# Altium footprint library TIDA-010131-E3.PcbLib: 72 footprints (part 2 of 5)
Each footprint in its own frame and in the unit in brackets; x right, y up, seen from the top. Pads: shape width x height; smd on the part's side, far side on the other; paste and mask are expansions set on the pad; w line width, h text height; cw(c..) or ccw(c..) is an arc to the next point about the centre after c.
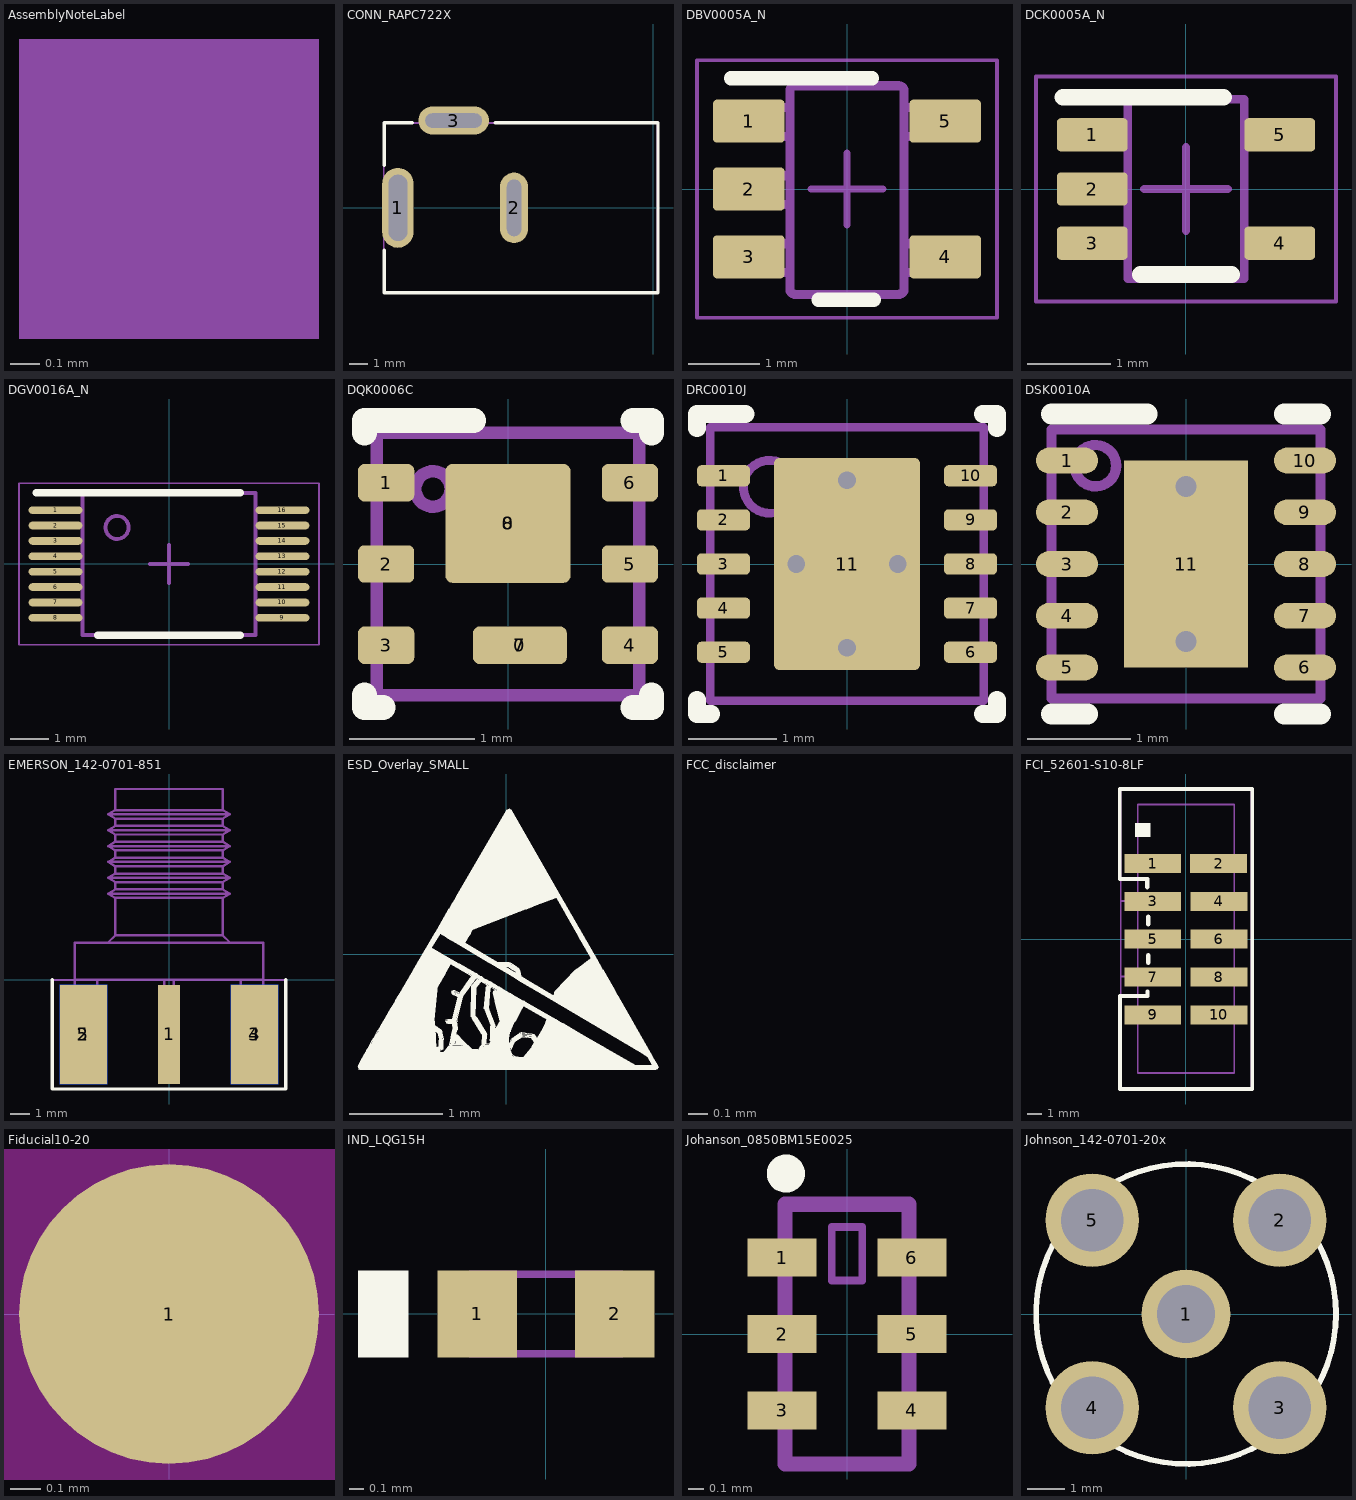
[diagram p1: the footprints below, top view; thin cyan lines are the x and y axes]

## AssemblyNoteLabel [mm] "Assembly Note for PCB Labels"
Mechanical 5:
  rectangle: 15.799,83.744 16.815,84.76
  text ".Designator" at 11.913,83.845 h0.64
  text "Install label in silkscreened box after final wash.  Text shall be 8 pt font.  Text shall be per the Label Table in the PDF schematic." at 17.755,83.896 h0.64

## CONN_RAPC722X [mm] "Conn_DC Jack"
height 11.176
pads (3):
  oval 1.7x4.3 hole 1.01 slot 3.56 at 90 deg: 1(-13.741,0)
  oval 1.5x3.8 hole 0.76 slot 3.05 at 90 deg: 2(-7.493,0)
  oval 3.8x1.5 hole 0.76 slot 3.05 at 0 deg: 3(-10.744,4.7)
Top Overlay:
  lines w0.178: -14.478,-2.286 -14.478,-4.572 0.254,-4.572 0.254,4.572 -8.509,4.572 ; -14.478,2.286 -14.478,4.572 -12.954,4.572
Mechanical 5:
  lines w0.102: -14.505,-4.572 -14.505,4.572 0.227,4.572 0.227,-4.572 -14.505,-4.572
  lines w0.127: -14.443,-1.5 -13.943,-1.5 ; -14.443,1.5 -13.943,1.5 ; -13.543,-1.5 -13.943,-1.5 ; -13.543,1.5 -13.943,1.5 ; -11.993,4.5 -11.993,4.9 -9.493,4.9 -9.493,4.5 ; -13.943,-1.5 -13.943,1.5
  text ".Designator" at -12.446,-0.508 h0.64
3D body: height 11.18, standoff 0, extent -14.504,-4.571 0.226,4.571
3D body: height 5.08, standoff -2.54, extent -7.62,-1.397 -7.366,1.397
3D body: height 5.08, standoff -2.54, extent -12.14,4.573 -9.346,4.827
3D body: height 5.08, standoff -2.54, extent -14.06,-1.651 -13.425,1.651

## DBV0005A_N [mm] "SOT23, 5-Leads, Body 2.9x1.6mm, Pitch 0.95mm, Lead Span 2.8mm, IPC Medium Density"
height 1.45
pads (5):
  rrect17% 1x0.6 smd: 1(-1.375,0.95) 2(-1.375,0) 3(-1.375,-0.95) 4(1.375,-0.95) 5(1.375,0.95)
Top Overlay:
  lines w0.2: -1.625,1.55 0.35,1.55 ; -0.4,-1.55 0.375,-1.55
Mechanical 5:
  lines w0.127: -0.801,1.371 cw(c-0.725,1.37) -0.725,1.446 ; -0.801,1.37 -0.801,1.371 ; -0.801,1.37 -0.801,-1.399 -0.801,-1.4 ccw(c-0.725,-1.399) -0.725,-1.475 ; -0.725,-1.475 0.723,-1.475 0.724,-1.475 ccw(c0.723,-1.399) 0.799,-1.4 0.799,-1.399 0.799,1.37 ; -0.725,-1.475 -0.725,-1.475 ; -0.725,1.446 -0.725,1.446 ; -0.725,1.446 0.723,1.446 0.724,1.446 cw(c0.723,1.37) 0.799,1.371 ; 0.799,1.37 0.799,1.371 ; -1.423,-1.167 -1.423,-0.767 -1.199,-0.767 -1.105,-0.767 -1.088,-0.767 -0.835,-0.767 -0.801,-0.767 -0.801,-1.167 -0.835,-1.167 -1.088,-1.167 -1.105,-1.167 -1.199,-1.167 -1.423,-1.167 ; -1.423,-0.215 -1.423,0.186 -1.199,0.186 -1.105,0.186 -1.088,0.186 -0.835,0.186 -0.801,0.186 -0.801,-0.215 -0.835,-0.215 -1.088,-0.215 -1.105,-0.215 -1.199,-0.215 -1.423,-0.215 ; -1.423,0.738 -1.423,1.138 -1.199,1.138 -1.105,1.138 -1.088,1.138 -0.835,1.138 -0.801,1.138 -0.801,0.738 -0.835,0.738 -1.088,0.738 -1.105,0.738 -1.199,0.738 -1.423,0.738 ; 0.799,-1.167 0.834,-1.167 1.087,-1.167 1.103,-1.167 1.198,-1.167 1.422,-1.167 1.422,-0.767 1.198,-0.767 1.103,-0.767 1.087,-0.767 0.834,-0.767 0.799,-0.767 0.799,-1.167 ; 0.799,0.738 0.834,0.738 1.087,0.738 1.103,0.738 1.198,0.738 1.422,0.738 1.422,1.138 1.198,1.138 1.103,1.138 1.087,1.138 0.834,1.138 0.799,1.138 0.799,0.738
  text ".Designator" at 0.356,-0.571 h0.64
Mechanical 15:
  lines w0.05: -2.1,-1.8 -2.1,1.8 2.1,1.8 2.1,-1.8 -2.1,-1.8
  lines w0.1: -0.5,0 0.5,0 ; 0,-0.5 0,0.5
3D body "DBV0005A.stp": height 1.09, standoff 0, extent -1.422,-1.461 1.423,1.46

## DCK0005A_N [mm] "SOT353, 5-Leads, Body 2x1.3mm, Pitch 0.65mm, Lead Span 2.1mm, IPC Medium Density"
height 1.1
pads (5):
  rrect25% 0.85x0.4 smd: 1(-1.125,0.65) 2(-1.125,0) 3(-1.125,-0.65) 4(1.125,-0.65) 5(1.125,0.65)
Top Overlay:
  lines w0.2: -1.475,1.1 0.45,1.1 ; -0.55,-1.025 0.55,-1.025
Mechanical 5:
  lines w0.1: -0.7,-1.075 0.7,-1.075 0.7,1.075 -0.7,1.075 -0.7,-1.075
  lines w0.127: -0.865,0.762 -0.853,0.762 ; -0.711,-0.763 -0.853,-0.763 -0.865,-0.763 -0.959,-0.763 -1.143,-0.763 -1.143,-0.538 -0.959,-0.538 -0.865,-0.538 -0.853,-0.538 -0.711,-0.538 ; -0.711,-0.113 -0.853,-0.113 -0.865,-0.113 -0.959,-0.113 -1.143,-0.113 -1.143,0.112 -0.959,0.112 -0.865,0.112 -0.853,0.112 -0.711,0.112 ; -0.711,0.537 -0.853,0.537 -0.865,0.537 -0.959,0.537 -1.143,0.537 -1.143,0.762 -0.959,0.762 -0.711,0.762 ; 0.711,-0.763 0.847,-0.763 0.859,-0.763 0.953,-0.763 1.137,-0.763 1.137,-0.538 0.953,-0.538 0.859,-0.538 0.847,-0.538 0.711,-0.538 ; 0.711,0.537 0.847,0.537 0.859,0.537 0.953,0.537 1.137,0.537 1.137,0.762 0.953,0.762 0.859,0.762 0.847,0.762 0.711,0.762
  text ".Designator" at -0.254,0.824 h0.64
Mechanical 15:
  lines w0.05: -1.8,-1.35 1.8,-1.35 1.8,1.35 -1.8,1.35 -1.8,-1.35
  lines w0.1: -0.5,0 0.5,0 ; 0,-0.5 0,0.5
3D body "DCK0005A.stp": height 0.95, standoff 0, extent -1.14,-1 1.14,1

## DGV0016A_N [mm] "TSSOP, 16-Leads, Body 3.6x4.4mm, Pitch 0.4mm, IPC Medium Density"
height 1.2
pads (16):
  oval 1.4x0.2 smd: 1(-2.95,1.4) 2(-2.95,1) 3(-2.95,0.6) 4(-2.95,0.2) 5(-2.95,-0.2) 6(-2.95,-0.6) 7(-2.95,-1) 8(-2.95,-1.4) 9(2.95,-1.4) 10(2.95,-1) 11(2.95,-0.6) 12(2.95,-0.2) 13(2.95,0.2) 14(2.95,0.6) 15(2.95,1) 16(2.95,1.4)
Top Overlay:
  lines w0.2: -3.45,1.85 1.85,1.85 ; -1.85,-1.85 1.85,-1.85
Mechanical 5:
  circle w0.1: c-1.35,0.95 r0.3
  lines w0.1: -2.25,-1.85 2.25,-1.85 2.25,1.85 -2.25,1.85 -2.25,-1.85
  text ".Designator" at 0.781,-0.032 h0.64
Mechanical 15:
  lines w0.05: -3.9,-2.1 3.9,-2.1 3.9,2.1 -3.9,2.1 -3.9,-2.1
  lines w0.1: -0.5,0 0.5,0 ; 0,-0.5 0,0.5
3D body "DGV0016A.stp": height 1.2, standoff 0, extent -3.209,-1.8 3.209,1.8

## DQK0006C [mm] "WSON"
height 0.8
pads (10):
  rrect50% 0.9x0.86 on Top Paste: 0(0,0.325)
  rrect50% 0.7x0.29 on Top Paste: 0(0.095,-0.65)
  rrect33% 0.45x0.3 smd: 1(-0.975,0.65) 2(-0.975,0) 3(-0.975,-0.65) 4(0.975,-0.65) 5(0.975,0) 6(0.975,0.65)
  rrect33% 0.75x0.3 smd paste-0.15: 7(0.095,-0.65)
  rrect11% 1x0.95 smd paste-0.5: 8(0,0.325)
Top Overlay:
  lines w0.2: -1.15,-1.05 -1.15,-1.15 -1,-1.15 ; -1.15,1.05 -1.15,1.15 -0.275,1.15 ; 1,-1.15 1.15,-1.15 1.15,-1.05 ; 1,1.15 1.15,1.15 1.15,1.05
Mechanical 5:
  circle w0.1: c-0.6,0.6 r0.141
  lines w0.1: -1.05,-1.05 -1.05,1.05 1.05,1.05 1.05,-1.05 -1.05,-1.05
  text ".Designator" at 0.397,-0.417 h0.64
3D body "DQK0006C.stp": height 0.82, standoff 0, extent -1,-1 1,1

## DRC0010J [mm] "SON, 10-Leads, Body 3x3mm, Pitch 0.5mm, Thermal Pad 2.4x1.65mm, TI Recommended"
height 1
pads (11):
  rrect42% 0.6x0.24 smd: 1(-1.4,1) 2(-1.4,0.5) 3(-1.4,0) 4(-1.4,-0.5) 5(-1.4,-1) 6(1.4,-1) 7(1.4,-0.5) 8(1.4,0) 9(1.4,0.5) 10(1.4,1)
  rrect6% 1.65x2.4 smd paste-0.825: 11(0,0)
via 0,-0.95 diameter 0.5 hole 0.2
via 0,0.95 diameter 0.5 hole 0.2
via 0.575,0 diameter 0.5 hole 0.2
via -0.575,0 diameter 0.5 hole 0.2
Top Overlay:
  lines w0.2: -1.7,-1.54 -1.7,-1.7 -1.54,-1.7 ; -1.7,1.54 -1.7,1.7 -1.15,1.7 ; 1.54,-1.7 1.7,-1.7 1.7,-1.54 ; 1.54,1.7 1.7,1.7 1.7,1.54
Top Paste:
  rectangle: -0.75,-1.16 0.75,-0.1
  rectangle: -0.75,0.1 0.75,1.16
Mechanical 5:
  circle w0.1: c-0.875,0.875 r0.3
  lines w0.1: -1.55,-1.55 -1.55,1.55 1.55,1.55 1.55,-1.55 -1.55,-1.55
  text ".Designator" at 0.496,0.077 h0.64
3D body "DRC0010J.stp": height 0.77, standoff 0, extent -1.5,-1.5 1.5,1.5

## DSK0010A [mm] "SON, 10-Leads, Body 2.5x2.5mm, Pitch 0.5mm, Thermal Pad 2x1.2mm - ADI"
height 0.8
pads (11):
  oval 0.6x0.25 smd: 1(-1.15,1) 2(-1.15,0.5) 3(-1.15,0) 4(-1.15,-0.5) 5(-1.15,-1) 6(1.15,-1) 7(1.15,-0.5) 8(1.15,0) 9(1.15,0.5) 10(1.15,1)
  rect 1.2x2 smd paste-0.6: 11(0,0)
via 0,0.75 diameter 0.5 hole 0.2
via 0,-0.75 diameter 0.5 hole 0.2
Top Overlay:
  lines w0.2: -1.3,-1.45 -0.95,-1.45 ; -1.3,1.45 -0.375,1.45 ; 0.95,-1.45 1.3,-1.45 ; 0.95,1.45 1.3,1.45
Top Paste:
  rectangle: -0.563,-0.894 0.563,0.895
Top Solder:
  region: -0.663,0.594 -0.663,1.064 0.663,1.064 0.663,0.594
  region: -0.663,-0.194 -0.663,0.194 0.663,0.194 0.663,-0.194
  region: -0.663,-1.064 -0.663,-0.594 0.663,-0.594 0.664,-1.064
  region: -0.663,-1.064 -0.663,1.064 -0.2,1.064 -0.2,-1.064
  region: 0.2,-1.064 0.2,1.064 0.663,1.064 0.664,-1.064
  region: 0,1
  region: 0,-1
Mechanical 5:
  circle w0.1: c-0.875,0.95 r0.2
  lines w0.1: -1.3,-1.3 1.3,-1.3 1.3,1.3 -1.3,1.3 -1.3,-1.3
  text ".Designator" at -1.016,-0.889 h0.51
3D body "DSK0010A.stp": height 0.8, standoff 0, extent -1.25,-1.25 1.25,1.25

## EMERSON_142-0701-851 [mil] "Johnson Components"
height 154
pads (5):
  rect 45x200 smd: 1(0,-110)
  rect 95x200 smd: 2(-172.5,-110) 3(172.5,-110)
  rect 95x200 smd far side: 4(172.5,-110) 5(-172.5,-110)
Top Overlay:
  lines w7: -235,0 -235,-220 -5,-220 235,-220 235,0
Mechanical 1:
  lines w3.94: -235,0 235,0
Mechanical 5:
  lines w5: -145,0 -145,-197 -190,-197 -190,0 ; -123.5,75 -108,90 ; -10,0 -10,-90 10,-90 10,0 ; 123.5,75 108,90 ; 145,0 145,-197 190,-197 190,0 ; -190,0 -190,75 190,75 190,0 ; -190,0 190,0 ; -123,173.9 0,173.9 123,173.9 ; -123,173.9 -108,182.56 ; -123,173.9 -108,165.24 ; -123,205.9 0,205.9 123,205.9 ; -123,205.9 -108,197.24 ; -123,205.9 -108,214.56 ; -123,237.9 0,237.9 123,237.9 ; -123,237.9 -108,246.56 ; -123,237.9 -108,229.24 ; -123,269.9 0,269.9 123,269.9 ; -123,269.9 -108,261.24 ; -123,269.9 -108,278.56 ; -123,301.9 0,301.9 123,301.9 ; -123,301.9 -108,310.56 ; -123,301.9 -108,293.24 ; -123,333.9 0,333.9 123,333.9 ; -123,333.9 -108,342.56 ; -123,333.9 -108,325.24 ; -108,90 108,90 ; -108,90 -108,165.24 ; -108,165.24 108,165.24 ; -108,182.56 108,182.56 ; -108,182.56 -108,197.24 ; -108,197.24 108,197.24 ; -108,214.56 108,214.56 ; -108,214.56 -108,229.24 ; -108,229.24 108,229.24 ; -108,246.56 108,246.56 ; -108,246.56 -108,261.24 ; -108,261.24 108,261.24 ; -108,278.56 108,278.56 ; -108,278.56 -108,293.24 ; -108,293.24 108,293.24 ; -108,310.56 108,310.56 ; -108,310.56 -108,325.24 ; -108,325.24 108,325.24 ; -108,342.56 108,342.56 ; -108,342.56 -108,385 108,385 108,342.56 ; 108,90 108,165.24 ; 108,165.24 123,173.9 ; 108,182.56 108,197.24 ; 108,182.56 123,173.9 ; 108,197.24 123,205.9 ; 108,214.56 108,229.24 ; 108,214.56 123,205.9 ; 108,229.24 123,237.9 ; 108,246.56 123,237.9 ; 108,246.56 108,261.24 ; 108,261.24 123,269.9 ; 108,278.56 123,269.9 ; 108,278.56 108,293.24 ; 108,293.24 123,301.9 ; 108,310.56 108,325.24 ; 108,310.56 123,301.9 ; 108,325.24 123,333.9 ; 108,342.56 123,333.9
  text ".Designator" at 239.5,-186.7 h25
3D body "Johnson_142-0701-851.stp": height 154.6, standoff -162.4, extent -190,-195 190,387

## ESD_Overlay_SMALL [mm]
height 9.53
Top Overlay:
  drawing of 901 lines, arcs and shapes, not listed

## FCC_disclaimer [mm]
height 9.53
Top Overlay:
  text "For evaluation only; not FCC approved for resale." at 17.426,17.153 h1.52

## FCI_52601-S10-8LF [mil] "FCI Electronics"
height 503
pads (10):
  rect 150x50 smd: 1(-87.5,200) 2(86.5,200) 3(-87.5,100) 4(87.5,100) 5(-87.5,0) 6(87.5,0) 7(-87.5,-100) 8(87.5,-100) 9(-87.5,-200) 10(87.5,-200)
Top Overlay:
  region: -93.2,307.14 -134.23,307.14 -134.23,269.66 -93.2,269.66
  lines w10: -101.5,-138 -101.5,-150 -174,-150 -174,-396 175.5,-396 175.5,397 -174.5,397 -174.5,159 -101.5,159
  lines w12: -101.5,138 -101.5,158 ; -99.5,-62 -99.5,-42 ; -99.5,39 -99.5,59
Mechanical 5:
  lines w5: -172,-99 -172,-394 173,-394 173,396 -172,396 -172,101 ; -172,-99 -172,-79 -172,81 -172,101 ; -172,-99 -127,-99 ; -172,101 -127,101 ; -127,-99 -127,-354 128,-354 128,356 -127,356 -127,101 ; -127,-99 -127,101
  text ".Designator" at 19.5,-37 h20
3D body "FCI_52601-X10-8LF.stp": height 495.6, standoff 0.6, extent -172.5,-395 172.5,395

## Fiducial10-20 [mm]
height 9.53
pads (1):
  round 1 smd mask+0.5: 1(0,0)
Top Layer keep-out:
  circle w1.178: c0,0 r0.5

## IND_LQG15H [mm] "MuRata"
height 0.55
pads (2):
  rect 0.55x0.6 smd: 1(-0.475,0) 2(0.475,0)
Top Overlay:
  rectangle: -1.3,-0.3 -0.95,0.3
Mechanical 5:
  rectangle: -0.7,-0.273 -0.525,0.277
  lines w0.05: -0.525,-0.275 0.525,-0.275 0.525,0.275 -0.525,0.275 -0.525,-0.275
  text ".Designator" at -0.996,0.271 h0.64
3D body: height 0.55, standoff 0, extent -0.524,-0.274 -0.276,0.274
3D body: height 0.54, standoff 0, extent -0.274,-0.274 0.274,0.274
3D body: height 0.55, standoff 0, extent 0.276,-0.274 0.524,0.274
3D body: height 0.55, standoff 0.54, extent -0.274,-0.274 -0.001,0.274

## Johanson_0850BM15E0025 [mm] "SMD, 6-Leads, Body 1.6x0.8mm, Pitch 0.5mm"
height 0.7
pads (6):
  rect 0.45x0.25 smd: 1(-0.425,0.5) 2(-0.425,0) 3(-0.425,-0.5) 4(0.425,-0.5) 5(0.425,0) 6(0.425,0.5)
Top Overlay:
  circle w0.125: c-0.4,1.05 r0.062
Mechanical 5:
  lines w0.05: -0.1,0.35 -0.1,0.7 0.1,0.7 0.1,0.35 -0.1,0.35
  lines w0.1: -0.405,-0.85 0.405,-0.85 0.405,0.85 -0.405,0.85 -0.405,-0.85
  text ".Designator" at -0.4,-0.2 h0.5
3D body: height 0.7, standoff 0, extent -0.405,-0.85 0.405,0.85
3D body: height 0.7, standoff 0.7, extent -0.1,0.35 0.1,0.7

## Johnson_142-0701-20x [mil] "Johnson Components recommended land pattern"
height 375
pads (5):
  round 95 hole 62: 1(0,0)
  round 100 hole 67: 2(100,100) 3(100,-100) 4(-100,-100) 5(-100,100)
Top Overlay:
  circle w6: c0,0 r160
Mechanical 5:
  circle w5: c0,0 r160
  text ".Designator" at -60,-30 h25
3D body "Emerson_142-0701-201.stp": height 375, standoff -155, extent -155.99,-155.8 156.01,155.8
